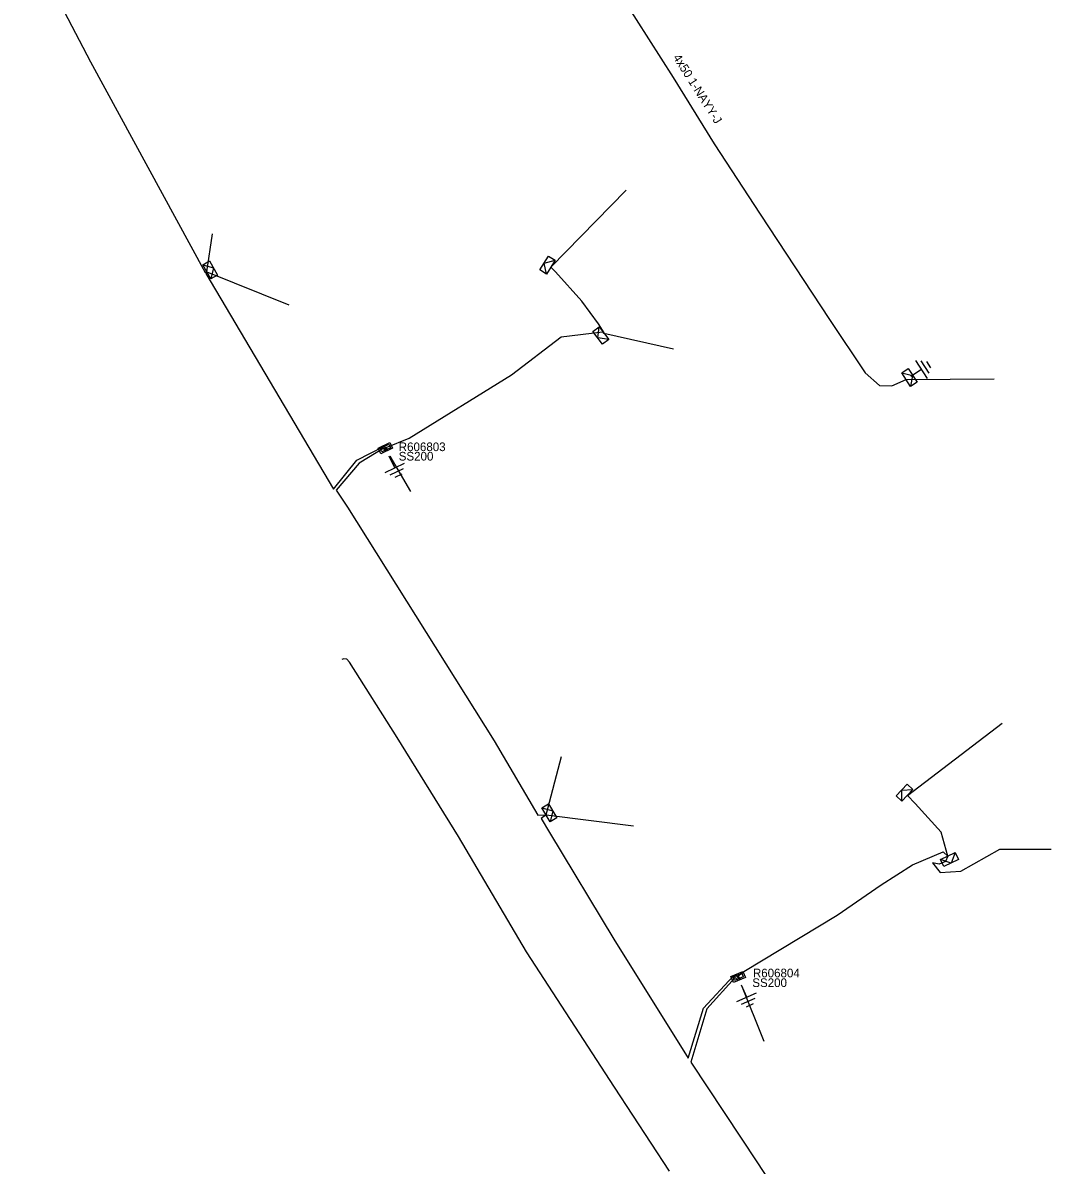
# Model space of a CAD drawing. Extents: x -540028 to -538776, y -1157064 to -1155670.
# Drawn here: x -539795.6 to -539676.5, y -1156719.5 to -1156587.3 of the extents above; entities that cross this region are included whole.
import ezdxf

# ---------------------------------------------------------------- set-up
doc = ezdxf.new("R2010")
doc.units = 0
for name, color, linetype in [('Vrstva 15', 7, 'Continuous'), ('Vrstva 2', 7, 'Continuous'), ('Vrstva 28', 7, 'Continuous'), ('Vrstva 29', 7, 'Continuous'), ('Vrstva 30', 7, 'Continuous'), ('Vrstva 31', 7, 'Continuous'), ('Vrstva 5', 7, 'Continuous'), ('Vrstva 52', 7, 'Continuous'), ('Vrstva 59', 7, 'Continuous'), ('Vrstva 6', 7, 'Continuous')]:
    doc.layers.add(name, color=color, linetype=linetype)

# ---------------------------------------------------------------- blocks, each defined once
blk = doc.blocks.new('132')
at = {"layer": 'Vrstva 2'}
for points in [[(-1.5, 1.5), (1.5, 1.5), (1.5, 0), (-1.5, 0)], [(-1.1, 1.2), (1.1, 1.2), (1.1, 0.3), (-1.1, 0.3)]]:
    blk.add_lwpolyline(points, close=True, dxfattribs=at)
blk = doc.blocks.new('23')
at = {"layer": 'Vrstva 2'}
blk.add_lwpolyline([(1.875, -1.8), (-1.875, -1.8), (-1.875, 0), (1.875, 0)], close=True, dxfattribs=at)
blk.add_lwpolyline([(1.875, 0), (0, -1.8), (-1.875, 0)], dxfattribs=at)
blk = doc.blocks.new('11')
at = {"layer": 'Vrstva 2'}
for p, q in [((0, -4.3), (0, -1.3)), ((-2.5, -4.3), (2.5, -4.3)), ((-1.7, -5.3), (1.7, -5.3)), ((-0.9, -6.3), (0.9, -6.3))]:
    blk.add_line(p, q, dxfattribs=at)

msp = doc.modelspace()

# ---------------------------------------------------------------- linework, layer by layer
at = {"layer": 'Vrstva 5'}
for points in [[(-539748.12, -1156547.76), (-539748.15, -1156547.64), (-539747.65, -1156547.52), (-539745.99, -1156548.95), (-539744.7, -1156550.09), (-539744.42, -1156552.47), (-539740.91, -1156558.97), (-539733.54, -1156571.6), (-539725.99, -1156584.61), (-539720.28, -1156593.61), (-539715.52, -1156601.29), (-539710.21, -1156609.42), (-539702.18, -1156621.59), (-539698.05, -1156627.79), (-539696.4, -1156629.22), (-539694.94, -1156629.28), (-539693.3, -1156628.56)], [(-539792.14, -1156571.55), (-539792.67, -1156570.98), (-539794.72, -1156572.28), (-539795.56, -1156576.77), (-539787.72, -1156591.78), (-539774.46, -1156616.16), (-539774.26, -1156616.09), (-539774.39, -1156616.27), (-539759.6, -1156641.25), (-539756.91, -1156637.89), (-539753.73, -1156636.27), (-539753.42, -1156636.82)], [(-539753.31, -1156636.77), (-539753.5, -1156636.41), (-539750.83, -1156635.34), (-539738.97, -1156627.99), (-539733.22, -1156623.61), (-539728.45, -1156623.01), (-539728.32, -1156623.18), (-539728.28, -1156623.18), (-539728.26, -1156623.13), (-539728.92, -1156622.12), (-539730.84, -1156619.48), (-539733.91, -1156616.07), (-539734.43, -1156615.54)], [(-539753.53, -1156636.87), (-539753.75, -1156636.48), (-539756.61, -1156638.21), (-539759.28, -1156641.34), (-539757.99, -1156643.3), (-539741.01, -1156670.36), (-539735.95, -1156678.97), (-539734.98, -1156678.92), (-539735.54, -1156679.35), (-539734.58, -1156680.96), (-539727.13, -1156693.29), (-539718.54, -1156707.09), (-539716.77, -1156701.3), (-539713.34, -1156697.59), (-539713.02, -1156697.44), (-539712.6, -1156698.02)], [(-539712.47, -1156697.97), (-539712.73, -1156697.54), (-539712.08, -1156697.05), (-539701.3, -1156690.52), (-539696.18, -1156687), (-539692.56, -1156684.7), (-539689.03, -1156683.21), (-539688.47, -1156683.68)], [(-539712.73, -1156698.08), (-539713.1, -1156697.73), (-539716.39, -1156701.36), (-539718.22, -1156707.53), (-539710.49, -1156719.2), (-539708.62, -1156722.06), (-539708.34, -1156722.67), (-539708.47, -1156723.11)]]:
    msp.add_lwpolyline(points, dxfattribs=at)
at = {"layer": 'Vrstva 52'}
for points in [[(-539753.06, -1156637.42), (-539750.66, -1156641.49)], [(-539720.71, -1156720.13), (-539727.06, -1156710.42), (-539737.24, -1156694.78), (-539745.14, -1156681.42), (-539752.23, -1156669.98), (-539757.73, -1156661.26), (-539758.06, -1156660.92), (-539758.38, -1156660.87), (-539758.62, -1156660.95)], [(-539688.47, -1156683.68), (-539689.25, -1156680.91), (-539692.26, -1156677.61), (-539693.15, -1156676.66)], [(-539688.47, -1156683.68), (-539688.76, -1156684.3), (-539689.49, -1156684.64), (-539690.24, -1156684.46)]]:
    msp.add_lwpolyline(points, dxfattribs=at)
at = {"layer": 'Vrstva 59'}
for points in [[(-539734.43, -1156615.54), (-539725.7, -1156606.64)], [(-539774.26, -1156616.09), (-539773.61, -1156611.67)], [(-539774.26, -1156616.09), (-539764.78, -1156619.89)], [(-539728.28, -1156623.18), (-539720.22, -1156625)], [(-539693.3, -1156628.56), (-539683.12, -1156628.47)], [(-539693.15, -1156676.66), (-539682.18, -1156668.31)], [(-539734.98, -1156678.92), (-539733.18, -1156672.16)], [(-539734.98, -1156678.92), (-539724.85, -1156680.18)], [(-539690.24, -1156684.46), (-539689.36, -1156685.6), (-539686.98, -1156685.44), (-539682.45, -1156682.89), (-539676.51, -1156682.9)], [(-539712.34, -1156698.67), (-539709.78, -1156705.09)]]:
    msp.add_lwpolyline(points, dxfattribs=at)

# ---------------------------------------------------------------- block references
at = {"layer": 'Vrstva 15'}
for p, xscale, yscale, rotation in [((-539693.3, -1156628.56), 0.5000000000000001, 0.4999999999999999, 123.37595268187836), ((-539753.42, -1156636.82), 0.5, 0.5, 25.999999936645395), ((-539712.6, -1156698.04), 0.49999999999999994, 0.5, 23.000000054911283)]:
    msp.add_blockref('11', p, dxfattribs=dict(at, xscale=xscale, yscale=yscale, rotation=rotation))
at = {"layer": 'Vrstva 28'}
for p, xscale, yscale, rotation in [((-539753.42, -1156636.82), 0.5, 0.5000000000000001, 26.00000008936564), ((-539712.6, -1156698.02), 0.49999999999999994, 0.5, 23.000000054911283)]:
    msp.add_blockref('132', p, dxfattribs=dict(at, xscale=xscale, yscale=yscale, rotation=rotation))
at = {"layer": 'Vrstva 31'}
for p, xscale, yscale, rotation in [((-539774.26, -1156616.09), 0.49999999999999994, 0.5, 120.00000002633), ((-539734.43, -1156615.54), 0.5, 0.5, -121.99999994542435), ((-539728.28, -1156623.18), 0.49999999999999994, 0.5000000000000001, -52.999999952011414), ((-539693.3, -1156628.56), 0.5000000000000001, 0.4999999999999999, 123.37595268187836), ((-539693.15, -1156676.66), 0.5, 0.5, -132.9999999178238), ((-539734.98, -1156678.92), 0.5, 0.5, 121.00000008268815), ((-539688.47, -1156683.68), 0.5, 0.5000000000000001, 24.9999999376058)]:
    msp.add_blockref('23', p, dxfattribs=dict(at, xscale=xscale, yscale=yscale, rotation=rotation))

# ---------------------------------------------------------------- texts
at = {"layer": 'Vrstva 29'}
for s, p in [('R606803', (-539752.04, -1156636.83)), ('R606804', (-539711.04, -1156697.72))]:
    msp.add_text(s, height=1, dxfattribs=at).set_placement(p)
at = {"layer": 'Vrstva 30'}
for p in [(-539752.04, -1156637.92), (-539711.11, -1156698.84)]:
    msp.add_text('SS200', height=1, dxfattribs=at).set_placement(p)
at = {"layer": 'Vrstva 6'}
msp.add_text('4x50 1-NAYY-J', height=1, rotation=302.393, dxfattribs=at).set_placement((-539720.33, -1156591.28))

doc.saveas('drawing.dxf')
